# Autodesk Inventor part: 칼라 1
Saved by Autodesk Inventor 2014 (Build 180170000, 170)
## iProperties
Created: 2026-04
Part Number: 칼라 1
Material: 강철, 연강
Document SubType Name: Modeling
Designer: dg
Density: 7.86 g/cm^3
Appearance: 강철
Mass: 9.50677 g
Surface Area: 14.3956 cm^2
Volume: 1.20951 cm^3
Author: jhkim
Creation Date: 2026-03-27
Sending System: Autodesk Inventor 2026
Preprocessor: ST-DEVELOPER v20.1
Author: dg
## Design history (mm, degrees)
node "칼라 11"
node "솔리드1"
node "기준1"
